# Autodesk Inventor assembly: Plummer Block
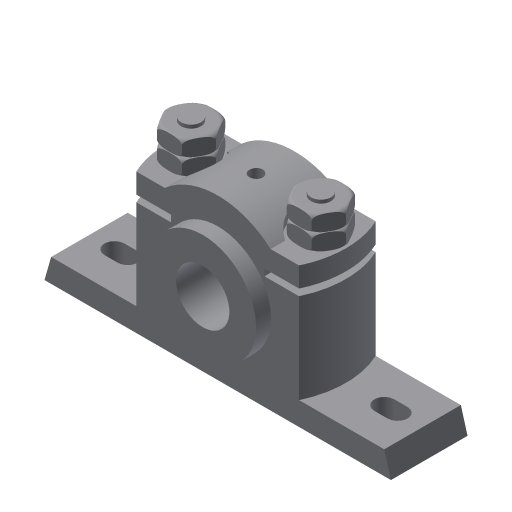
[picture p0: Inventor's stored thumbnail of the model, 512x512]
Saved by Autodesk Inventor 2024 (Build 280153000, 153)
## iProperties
Created: 2011-07
Part Number: Plummer Block
Document SubType Name: Assembly
Designer: CadCim
Author: CadCim
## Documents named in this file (7)
- D:\PROJECTS\Project 2023\RESOURCES INVENTOR 2024\RESOURCES INVENTOR 2024\Inventor_2023_Part\Inventor_2024_Part\c11_Inv_2024_prt\c11_Inv_2024_prt\fig 11-40 through 11-45\Plummer Block.iam
- D:\PROJECTS\Project 2023\RESOURCES INVENTOR 2024\RESOURCES INVENTOR 2024\Inventor_2023_Part\Inventor_2024_Part\c11_Inv_2024_prt\c11_Inv_2024_prt\fig 11-40 through 11-45\Casting.ipt
- D:\PROJECTS\Project 2023\RESOURCES INVENTOR 2024\RESOURCES INVENTOR 2024\Inventor_2023_Part\Inventor_2024_Part\c11_Inv_2024_prt\c11_Inv_2024_prt\fig 11-40 through 11-45\Brasses.ipt
- D:\PROJECTS\Project 2023\RESOURCES INVENTOR 2024\RESOURCES INVENTOR 2024\Inventor_2023_Part\Inventor_2024_Part\c11_Inv_2024_prt\c11_Inv_2024_prt\fig 11-40 through 11-45\Cap.ipt
- D:\PROJECTS\Project 2023\RESOURCES INVENTOR 2024\RESOURCES INVENTOR 2024\Inventor_2023_Part\Inventor_2024_Part\c11_Inv_2024_prt\c11_Inv_2024_prt\fig 11-40 through 11-45\Bolt.ipt
- D:\PROJECTS\Project 2023\RESOURCES INVENTOR 2024\RESOURCES INVENTOR 2024\Inventor_2023_Part\Inventor_2024_Part\c11_Inv_2024_prt\c11_Inv_2024_prt\fig 11-40 through 11-45\Nut.ipt
- D:\PROJECTS\Project 2023\RESOURCES INVENTOR 2024\RESOURCES INVENTOR 2024\Inventor_2023_Part\Inventor_2024_Part\c11_Inv_2024_prt\c11_Inv_2024_prt\fig 11-40 through 11-45\Lock Nut.ipt
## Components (9 placed, 6 different names)
1. Casting:1 — Mate:1, Mate:2, Insert:1, Insert:2, Angle:1, Angle:2
2. Brasses:1 — Mate:1, Mate:2, Mate:3, Mate:4
3. Cap:1 — Mate:3, Mate:4, Insert:3, Insert:4
4. Bolt:1 — Insert:1, Angle:1
5. Bolt:2 — Insert:2, Angle:2
6. Nut:1 — Insert:3, Insert:6
7. Nut:2 — Insert:4, Insert:5
8. Lock Nut:1 — Insert:6
9. Lock Nut:2 — Insert:5
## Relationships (12: Insert 6, Mate 4, Angle 2)
- Mate:1: Casting:1 ↔ Brasses:1
- Mate:2: Casting:1 ↔ Brasses:1
- Mate:3: Brasses:1 ↔ Cap:1
- Mate:4: Brasses:1 ↔ Cap:1
- Insert:1: Casting:1 ↔ Bolt:1
- Insert:2: Casting:1 ↔ Bolt:2
- Angle:1: Casting:1 ↔ Bolt:1
- Angle:2: Casting:1 ↔ Bolt:2
- Insert:3: Cap:1 ↔ Nut:1
- Insert:4: Cap:1 ↔ Nut:2
- Insert:5: Nut:2 ↔ Lock Nut:2
- Insert:6: Nut:1 ↔ Lock Nut:1
